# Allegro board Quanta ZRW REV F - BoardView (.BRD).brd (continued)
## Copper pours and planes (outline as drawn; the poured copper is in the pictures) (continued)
DAC_VDDC on TOP (solid shape): 18.69,109.07 18.71,109.05 18.71,108.95 18.78,108.88 19.83,108.88 19.83,108.68 18.84,108.68 18.84,108.48 19.83,108.48 19.83,108.28 18.73,108.28 18.56,108.12 18.17,108.12 18.04,108.25 18.04,109.12 18.2,109.29 18.48,109.29
DAC_VDDC on BOTTOM (solid shape): 19.22,109.47 19.22,109.37 19.24,109.34 19.24,106.73 19.14,106.63 18.25,106.63 18.2,106.68 16.95,106.68 16.85,106.78 16.85,107.31 16.98,107.44 18,107.44 18.17,107.62 18.17,109.34 18.35,109.52 19.16,109.52
EC_GND on SVCC (solid shape): 199.43,46.22 199.43,37 200.84,35.58 204.59,35.58 207.05,38.04 207.05,45.05 207.39,45.39 208.01,45.39 208.24,45.15 208.24,43.55 209.58,42.21 212.5,42.21 212.79,41.92 212.79,33.48 211.92,32.61 209.43,32.61 208.77,31.95 194.64,31.95 193.19,33.4 190.4,33.4 190.4,39.71 190.18,39.71 189.52,40.36 189.52,42.28 196.06,48.81 196.83,48.81
ECAGND on TOP (solid shape): 195.92,32.25 195.92,31.49 195.8,31.36 193.89,31.36 193.76,31.49 193.76,31.87 194.02,32.13 194.27,32.13 194.65,32.51 195.67,32.51
ECAGND on TOP (solid shape): 197.26,37.99 197.26,37.59 197.2,37.53 196.82,37.53 196.64,37.71 196.08,37.71 195.83,37.46 194.65,37.46 194.53,37.59 194.53,37.71 195.54,38.73 196.51,38.73
ECAGND on IN2 (solid shape): outline of 290 points within 193.26,31.36 196.68,38.6
HDMI_5V on TOP (solid shape): 17.24,74.5 17.24,73.32 17.12,73.19 12.39,73.19 12.2,73.39 12.2,74.48 12.36,74.64 17.1,74.64
HDMI_5V on IN2 (solid shape): 13.41,73.77 13.41,73.26 13.09,72.94 12.8,72.83 12.69,72.54 11.47,71.32 10.3,71.32 10.09,71.53 10.09,72.15 10.1,72.16 10.1,72.55 11.58,74.02 13.15,74.02
IVDDO on BOTTOM (solid shape): 17.72,106.09 17.72,106.04 17.87,105.89 17.87,105.28 17.73,105.14 17.61,105.14 17.55,105.09 17.55,104.15 17.23,103.83 16.4,103.83 16.27,103.96 16.27,106.02 16.62,106.37 17.44,106.37
IVDDO on BOTTOM (solid shape): 25.95,113.43 25.95,112.62 25.77,112.44 25.39,112.44 25.21,112.26 25.21,111.88 25.08,111.76 24.52,111.76 24.32,111.55 23.66,111.55 23.2,112.01 23.2,112.57 23.33,112.7 24.07,112.7 24.32,112.95 24.32,113.61 24.37,113.66 25.72,113.66
IVDDO on IN2 (solid shape): 26.25,113.15 26.25,112.39 25.74,111.88 24.98,111.88 24.22,112.64 24.22,113.41 24.47,113.66 25.74,113.66
IVDDO on IN2 (solid shape): 18.58,106.42 18.58,105.15 18.33,104.9 16.93,104.9 16.68,105.15 16.68,106.55 16.93,106.8 18.2,106.8
L_SPK+ on TOP (solid shape): 60.39,19.02 60.39,17.13 60.14,16.88 60.14,15.88 60,15.74 59.26,15.74 59.06,15.94 59.06,18.25 59.93,19.12 60.29,19.12
L_SPK+ on TOP (solid shape): 38.67,33.78 38.67,33.55 38.54,33.42 37.38,33.42 37.19,33.6 37.17,33.63 36.61,33.63 36.59,33.6 35.21,33.6 35.21,33.81 37.61,33.81 37.73,33.93 38.52,33.93
L_SPK+ on IN1 (solid shape): 61.09,20.04 61.09,18.13 60.89,17.93 59.96,17.93 59.82,18.06 59.82,19.86 59.84,19.9 60.24,20.29 60.85,20.29
L_SPK+ on IN1 (solid shape): 41.85,34.13 41.85,33.75 41.52,33.42 37.66,33.42 37.53,33.55 37.53,33.8 37.66,33.93 38.98,33.93 39.05,33.93 39.51,34.39 41.59,34.39
L_SPK+_1 on TOP (solid shape): 61.73,16.58 61.73,14.27 61.55,14.09 60.71,14.09 60.61,14.19 60.61,16.76 61.55,16.76
L_SPK+_1 on BOTTOM (solid shape): 62.7,17.09 62.7,14.47 61.99,13.76 61.56,13.76 61.21,14.11 60.71,14.11 60.59,14.24 60.59,15.13 60.84,15.38 61.91,15.38 62.09,15.56 62.09,17.09 62.12,17.12 62.67,17.12
L_SPK- on TOP (solid shape): 63.33,19.31 63.33,17.88 63.12,17.67 63.12,17.46 63.05,17.39 61.88,17.39 61.69,17.58 61.69,19.31 61.86,19.48 63.16,19.48
L_SPK- on TOP (solid shape): 38.67,34.62 38.67,34.21 38.54,34.08 37.68,34.08 37.6,34.01 36.2,34.01 36.2,34 35.21,34 35.21,34.21 36.2,34.21 36.24,34.2 36.24,34.21 37.38,34.21 37.66,34.49 37.66,34.6 37.8,34.74 38.54,34.74
L_SPK- on IN1 (solid shape): 63.25,20.72 63.25,19.07 62.87,18.69 61.86,18.69 61.6,18.94 61.6,19.93 61.78,20.11 61.78,20.11 62.52,20.84 63.13,20.84
L_SPK- on IN1 (solid shape): 41.03,35.28 41.03,35 40.79,34.76 39.45,34.76 38.87,34.18 37.81,34.18 37.63,34.36 37.63,34.62 37.76,34.74 38.44,34.74 39.18,35.48 40.83,35.48
L_SPK-_1 on TOP (solid shape): 63.07,16.83 63.07,14.55 63.2,14.42 63.2,13.55 62.99,13.34 62.22,13.34 62.03,13.53 62.03,16.81 62.14,16.91 63,16.91
L_SPK-_1 on BOTTOM (solid shape): 63.81,17.05 63.81,13.53 63.38,13.1 62.49,13.1 62.28,13.31 62.28,13.67 63.03,14.42 63.03,14.43 63.09,14.49 63.09,17.04 63.17,17.12 63.74,17.12
LAN_MCT1 on TOP (solid shape): 17.84,90.17 17.84,89.53 17.72,89.4 17.08,89.4 17.05,89.41 17.04,89.43 16.67,89.43 16.44,89.66 16.44,90.89 16.68,91.13 16.88,91.13
LAN_MCT2 on TOP (solid shape): 18,87.37 18,86.74 17.87,86.61 17.23,86.61 17.21,86.62 17.19,86.63 16.95,86.85 16.64,86.96 16.62,86.97 16.47,87.12 16.47,87.98 16.83,88.34 17.03,88.34
LAN_MCT3 on TOP (solid shape): 18.02,84.25 18.02,83.31 17.13,82.42 16.52,82.42 16.42,82.52 16.42,84.04 16.82,84.04 16.93,84.15 16.95,84.15 17.18,84.37 17.89,84.37
LANVCC on TOP (solid shape): 35.4,83.14 36.25,82.29 36.25,81.6 35.91,81.25 35.14,81.25 34.86,81.53 34.86,83.43 35.14,83.71 35.14,84.02 35.14,84.45 35.2,84.51 35.2,85.51 35.4,85.51
LANVCC on TOP (solid shape): 32.6,95.75 32.6,94.61 31.84,93.85 31.84,91.57 31.84,91.57 31.84,91.31 32.35,90.8 32.73,90.8 33.82,89.71 34.6,89.71 34.6,88.72 34.43,88.72 34.4,88.75 33.9,89.25 33.64,89.25 32.92,89.97 32.83,89.97 32.77,90.01 32.7,90.04 32.68,90.04 32.48,90.25 31.65,90.25 31.19,89.78 30.31,89.78 30.19,89.91 30.19,95.25 30.95,96.01 32.35,96.01
LANVCC on TOP (solid shape): 44.84,93.16 44.84,90.29 43.94,89.39 43.94,88.48 43.83,88.36 41.44,88.36 40.96,87.88 39.48,87.88 39.35,88.02 37.51,88.02 37.51,88.22 38.5,88.22 38.6,88.31 38.6,88.32 39.03,88.74 39.38,88.74 39.48,88.85 40.3,88.85 40.5,89.05 40.5,89.28 40.73,89.51 41.47,89.51 41.67,89.71 42.43,89.71 42.63,89.91 42.63,90.93 42.09,91.47 41.78,91.47 41.24,92.02 41.24,93.14 41.34,93.24 44.77,93.24
LANVCC on BOTTOM (solid shape): 32.73,96.52 32.73,95.37 31.71,94.36 30.44,94.36 30.19,94.61 30.19,95.12 31.84,96.77 32.47,96.77
LANVCC on BOTTOM (solid shape): 45.55,93.72 45.55,87.5 45.3,87.24 44.79,87.24 44.54,87.5 44.54,88.51 44.28,88.77 43.4,88.77 42.25,89.91 42.25,93.72 42.76,94.23 45.05,94.23
LANVCC on IN1 (solid shape): 43.78,91.97 43.78,86.62 43.76,86.61 43.76,86.08 39.23,81.55 37.28,81.55 37.19,81.45 35.72,81.45 35.67,81.5 35.67,82.62 35.73,82.68 35.91,82.68 36.04,82.66 36.17,82.68 36.78,82.68 36.92,82.82 36.92,82.82 37.51,83.41 38.86,83.41 42.33,86.89 42.47,86.98 42.58,87.24 42.56,87.37 42.56,87.83 42.58,87.96 42.56,88.08 42.56,90.03 42.46,90.14 42.46,92.02 42.58,92.15 43.6,92.15
LCDVCC on TOP (solid shape): 124.29,186.3 125.44,186.3 125.47,186.3 125.48,186.28 126.15,185.95 126.83,186.28 126.84,186.29 126.86,186.3 130.39,186.3 130.64,186.05 130.64,184.91 129.76,184.02 124.17,184.02 122.77,185.42 119.85,185.42 119.6,185.16 118.2,185.16 117.82,185.54 117.82,186.56 119.09,187.83 122.77,187.83
LCDVCC_R on TOP (solid shape): 132.55,186.56 132.55,184.78 132.4,184.63 132.37,184.62 132.1,184.66 131.89,184.54 131.88,184.53 131.86,184.53 131.53,184.53 131.28,184.78 131.28,186.69 131.53,186.94 132.17,186.94
LCDVCC_R on BOTTOM (solid shape): 130.93,186.74 131.36,186.74 131.53,186.91 132.37,186.91 132.65,186.64 132.65,185.85 132.37,185.57 130.22,185.57 129.22,186.99 129.22,187.04 129.4,187.17 129.41,187.17 130.06,186.24 130.07,186.24 130.26,186.38 130.26,186.38 129.61,187.3 129.61,187.32 129.8,187.45 129.82,187.45 130.46,186.53 130.48,186.53 130.67,186.66 130.67,186.67 130.02,187.59 130.02,187.6 130.22,187.74 130.23,187.74
NV_PLLVDD on TOP (solid shape): outline of 108 points within 183.89,142.44 185.94,150.8
PEX_PLLVDD on IN2 (solid shape): 172.45,160.11 172.73,159.75 173.15,159.91 173.24,159.95 173.32,159.91 173.49,159.78 173.71,159.76 174.07,159.4 174.26,158.94 174.75,159.06 174.84,159.1 174.92,159.05 175.17,158.86 175.48,158.93 176.04,158.93 176.54,158.43 176.54,157.55 176.28,157.29 175.91,157.29 175.63,157.57 175.63,157.6 175.5,157.94 175.15,158.01 175.14,158.01 174.46,158.01 174.45,158.01 174.02,158.44 174.02,158.46 173.78,158.82 173.36,158.72 172.35,158.72 171.55,159.52 171.55,159.53 169.88,161.19 167.83,161.19 167.56,161.46 167.56,161.8 167.63,161.87 170.69,161.87
PHASE_A on BOTTOM (solid shape): 147.92,169.03 147.92,167.76 147.28,167.13 146.82,167.13 146.77,167.18 146.77,167.76 147.03,168.02 147.03,169.03 147.15,169.16 147.79,169.16
PHASE_A on BOTTOM (solid shape): 147.77,162.61 147.77,158.99 147.46,158.68 145.55,158.68 145.27,158.97 145.27,159.73 145.28,159.74 145.28,160.47 145.26,160.47 145.26,160.65 144.73,160.65 144.73,160.47 144.72,160.47 144.72,158.96 144.44,158.68 142.31,158.68 142.12,158.88 142.12,160.65 143.37,161.91 143.37,162.23 143.54,162.4 144.65,162.4 145,162.75 145,163.04 145.15,163.18 147.2,163.18
PHASE_B1 on BOTTOM (solid shape): 127.72,170.3 127.72,169.54 127.47,169.29 127.47,168.91 127.09,168.52 126.63,168.52 126.58,168.58 126.58,170.18 126.83,170.43 127.6,170.43
PHASE_B1 on BOTTOM (solid shape): 129.25,162.68 129.25,160.72 128.87,160.34 127.74,160.34 127.7,160.36 127.69,160.39 127.69,161.92 127.15,161.92 127.15,160.39 127.14,160.36 127.1,160.34 124.86,160.34 124.37,160.83 124.37,163.98 124.96,164.58 127.36,164.58
PHASE_B2 on BOTTOM (solid shape): 136.99,169.16 136.99,167.89 136.36,167.25 135.9,167.25 135.85,167.31 135.85,167.89 136.23,168.27 136.23,169.16 136.36,169.29 136.87,169.29
PHASE_B2 on BOTTOM (solid shape): 138.61,161.32 138.61,159.26 138.27,158.92 137.05,158.92 136.59,159.38 136.59,160.59 136.58,160.6 136.58,160.78 136.04,160.78 136.04,160.61 136.03,160.59 136.03,159.45 135.49,158.92 134.02,158.92 133.62,159.32 133.62,162 134.23,162.62 134.23,163.26 134.25,163.29 134.28,163.31 136.62,163.31
PHASE_C on BOTTOM (solid shape): 158.97,169.03 158.97,167.89 158.2,167.13 157.62,167.13 157.57,167.18 157.57,168.91 157.82,169.16 158.84,169.16
PHASE_C on BOTTOM (solid shape): 159.6,162.01 159.6,159.22 159.04,158.65 157.76,158.65 157.59,158.83 157.59,160.46 157.58,160.47 157.58,160.65 157.05,160.65 157.05,160.48 157.03,160.48 157.03,158.87 156.82,158.66 155.3,158.66 154.84,159.12 154.84,161.39 155.95,162.49 155.95,163.13 155.96,163.16 156,163.18 158.43,163.18
R_SPK+ on TOP (solid shape): 67.6,19.2 67.6,17.3 66.75,17.3 66.75,17.16 66.07,17.16 65.79,17.44 65.79,19.29 65.93,19.43 67.37,19.43
R_SPK+ on TOP (solid shape): 37.55,35.94 37.55,35.76 37.27,35.48 37.27,35.15 36.93,34.8 35.21,34.8 35.21,35.01 36.57,35.01 36.77,35.2 36.77,35.4 37.05,35.68 37.05,35.89 37.22,36.06 37.43,36.06
R_SPK+ on IN1 (solid shape): 67.56,19.04 67.56,16.8 66.66,15.9 65.26,15.9 65.16,16 65.16,17.54 65.54,17.92 65.54,19.07 65.93,19.45 67.14,19.45
R_SPK+ on IN1 (solid shape): 39.71,38.6 39.71,38.07 38.28,36.63 37.79,36.59 37.75,36.1 37.25,35.61 37.25,35.56 37.21,35.52 37.21,34.96 37.05,34.79 36.54,34.79 36.41,34.92 36.41,36.83 38.32,38.73 39.59,38.73
R_SPK+_1 on TOP (solid shape): 67.57,16.78 67.57,13.61 67.44,13.48 66.68,13.48 66.55,13.61 66.55,16.83 66.58,16.86 67.49,16.86
R_SPK+_1 on BOTTOM (solid shape): 65.82,17.04 65.82,15.64 65.97,15.5 67.35,15.5 67.57,15.28 67.57,13.61 67.42,13.45 66.64,13.45 66.13,13.96 65.44,13.96 65.09,14.31 65.09,17.06 65.17,17.14 65.72,17.14
R_SPK- on TOP (solid shape): 65.31,18.53 65.31,17.57 65.16,17.42 64.01,17.42 63.86,17.57 63.86,17.67 63.61,17.92 63.61,18.56 63.91,18.86 64.98,18.86
R_SPK- on TOP (solid shape): 38.52,35.43 38.52,35.12 38.29,34.9 37.76,34.9 37.51,34.64 37.51,34.63 37.28,34.4 35.21,34.4 35.21,34.61 36.99,34.61 37.41,35.04 37.41,35.37 37.6,35.56 38.39,35.56
R_SPK- on IN1 (solid shape): 65.03,19.7 65.03,17.8 64.65,17.42 63.89,17.42 63.86,17.44 63.79,17.75 63.51,17.9 63.51,19.45 63.89,19.83 64.9,19.83
R_SPK- on IN1 (solid shape): 41.74,37.97 41.74,37.53 41.66,37.45 41.61,37.35 40.04,35.78 39.1,35.78 38.39,35.07 37.53,35.07 37.46,35.14 37.46,35.42 37.99,35.94 38.33,36.05 38.44,36.39 38.65,36.6 39.08,36.6 39.31,36.83 39.5,36.83 39.9,36.99 39.9,37.42 40.58,38.1 41.62,38.1
R_SPK-_1 on TOP (solid shape): 65.34,16.83 65.34,13.5 65.03,13.2 64.45,13.2 64.29,13.35 64.29,16.78 64.4,16.88 65.28,16.88
R_SPK-_1 on BOTTOM (solid shape): 64.7,17.07 64.7,14.41 65.24,13.87 65.24,13.56 64.81,13.13 64.18,13.13 64.09,13.22 64.09,17.07 64.16,17.14 64.63,17.14
REGOUT on TOP (solid shape): 40.81,93.11 40.81,91.36 40.2,90.75 40.2,90.52 40.09,90.42 39.71,90.42 39.47,90.18 39.47,89.24 39.13,88.9 38.77,88.9 38.5,88.62 38.5,88.42 37.51,88.42 37.51,88.59 37.73,88.81 37.73,90.29 39.28,91.84 39.28,93.06 39.41,93.19 40.73,93.19
RING2 on TOP (solid shape): 18.5,12.7 18.5,12.04 18.61,11.93 19.01,11.93 19.27,11.68 19.27,11.55 19.09,11.38 17.56,11.38 17.46,11.48 17.46,12.24 17.31,12.39 17.31,12.72 17.46,12.87 18.33,12.87
RING2 on TOP (solid shape): 28.84,35.51 28.84,34.77 29,34.61 30,34.61 30,34.41 30,34.4 29.01,34.4 28.79,34.4 28.28,34.91 28.28,35 28.08,35.2 27.72,35.2 27.6,35.33 27.6,35.63 27.75,35.78 28.56,35.78
RING2 on BOTTOM (solid shape): 18.5,14.09 18.5,12.57 18.25,12.31 17.36,12.31 17.11,12.57 17.11,14.09 17.23,14.22 18.38,14.22
RING2 on BOTTOM (solid shape): outline of 230 points within 27.19,28.09 31.53,36.7
RING2_R on TOP (solid shape): 17.16,11.91 17.16,11.12 17.49,10.79 18.38,10.79 18.5,10.66 18.5,9.93 18.32,9.75 14.95,9.75 14.66,10.04 14.66,10.96 15.25,11.55 15.25,11.88 15.33,11.96 17.11,11.96
RING2_R on IN1 (solid shape): 15.71,11.17 15.71,10.03 15.46,9.77 14.82,9.77 14.57,10.03 14.57,11.17 14.95,11.55 15.33,11.55
RREF on TOP (solid shape): 59.31,25.78 59.5,25.69 59.71,25.72 59.78,25.65 59.78,24.89 59.48,24.59 58.84,24.59 58.84,25.58 59.04,25.78
RX_AVCC on BOTTOM (solid shape): 26.12,110.99 26.12,106.47 25.79,106.14 24.75,106.14 24.6,106.29 24.6,111.5 25.62,111.5
RX_IVDD on TOP (solid shape): 20.23,105.49 20.23,105.49 20.23,104.72 20.05,104.54 19.62,104.54 19.44,104.72 19.44,105.02 19.6,105.18 19.85,105.18 20.03,105.36 20.03,106.48 20.23,106.48
RX_IVDD on BOTTOM (solid shape): 22.64,112.85 22.64,112.01 22.39,111.76 20.23,111.76 20.1,111.88 20.1,112.39 20.43,112.72 21.96,112.72 22.11,112.87 22.62,112.87
RX_IVDD on BOTTOM (solid shape): 19.37,106.04 19.37,105.63 19.44,105.56 19.44,105.25 19.34,105.15 18.91,105.15 18.83,105.08 18.83,104.29 18.78,104.24 18.02,104.24 18.02,105.66 18.53,106.17 19.24,106.17
RX_IVDD33 on TOP (solid shape): 26.99,112.87 26.99,110.13 26.17,110.13 26.05,110.26 25.54,110.26 25.46,110.18 25.34,110.18 25.34,111.17 26.28,112.11 26.28,112.82 26.4,112.95 26.91,112.95
S5D on BOTTOM (solid shape): 81.34,35.22 81.34,34.11 81.07,33.84 80.31,33.84 80.2,33.94 80.2,35.43 80.3,35.53 81.03,35.53
SLEEVE on TOP (solid shape): 28.62,34.21 30,34.21 30,34 28.91,34 28.8,33.9 27.55,33.9 27.39,34.05 27.39,34.67 27.52,34.79 28.03,34.79
SLEEVE on TOP (solid shape): 17.97,20.19 18,20.19 18.12,20.06 18.66,20.06 18.78,19.93 18.78,19.66 18.02,18.89 17.11,18.89 16.75,18.54 16.45,18.54 16.32,18.66 16.32,19.5 16.47,19.66 16.95,19.66 17.13,19.83 17.13,20.49 17.18,20.54 17.61,20.54
SLEEVE on BOTTOM (solid shape): 17.01,20.48 17.01,18.57 16.63,18.2 15.78,18.2 15.54,18.44 15.54,20.63 15.94,21.03 16.45,21.03
SLEEVE on BOTTOM (solid shape): 28.41,34.41 28.41,33.65 27.77,33.02 27.77,32.25 27.65,32.13 26.76,32.13 26.38,32.51 26.38,33.52 26.5,33.52 26.51,33.47 26.52,33.41 26.54,33.36 26.57,33.31 26.6,33.27 26.64,33.23 26.69,33.2 26.74,33.17 26.79,33.15 26.84,33.14 26.9,33.14 26.96,33.15 27.01,33.16 27.06,33.18 27.11,33.21 27.15,33.25 27.19,33.29 27.22,33.34 27.24,33.39 27.26,33.44 27.27,33.5 27.27,33.55 27.26,33.61 27.24,33.66 27.22,33.71 27.19,33.76 27.15,33.8 27.11,33.83 27.06,33.86 27.01,33.89 26.96,33.9 26.9,33.91 26.84,33.9 26.79,33.89 26.74,33.88 26.69,33.85 26.64,33.82 26.6,33.78 26.57,33.73 26.54,33.69 26.52,33.63 26.51,33.58 26.5,33.52 26.38,33.52 26.38,34.16 27.01,34.79 28.03,34.79
SLEEVE_R on TOP (solid shape): 16.7,20.52 16.7,20.14 16.65,20.09 16.04,20.09 15.66,19.71 15.15,19.71 15.02,19.83 13.65,19.83 13.04,20.44 13.04,20.57 13.27,20.8 14.74,20.8 15.48,21.54 15.68,21.54
SM_RCOMP_0 on IN1 (solid shape): outline of 236 points within 145.63,110.61 147.54,114.17
SM_RCOMP_1 on IN1 (solid shape): 147.75,112.64 147.84,112.6 147.85,112.51 147.85,112.32 147.94,112.15 147.97,112.08 147.84,111.76 147.97,111.43 147.94,111.36 147.84,111.03 148.06,110.77 148.07,110.77 148.42,110.41 148.42,109.98 148.04,109.6 147.79,109.6 147.61,109.78 147.61,111.57 147.62,111.93 147.31,112.13 147.29,112.13 147.15,112.26 147.15,112.52 147.28,112.64
SP_PLLVDD on TOP (solid shape): 184.7,151.23 184.7,150.87 184.52,150.69 184.19,150.69 183.65,150.16 183.65,142.46 183.58,142.39 183.17,142.39 183.02,142.54 183.02,142.87 182.36,143.53 182.36,144.19 182.49,144.32 182.49,146.1 182.77,146.38 182.77,147.01 182.46,147.32 182.46,148.79 182.87,149.2 182.87,150.49 183.64,151.27 184.66,151.27
SYSTEM_AGND on TOP (solid shape): 68.95,57.96 68.95,57.07 68.88,57 68.06,57 67.86,57.21 67.86,57.34 67.78,57.51 67.63,57.57 67.61,57.58 67.09,57.58 66.87,57.81 66.87,58.31 66.66,58.52 65.04,58.52 64.92,58.4 64.92,57.78 64.77,57.62 63.98,57.62 63.87,57.73 63.87,58.27 63.87,58.27 63.87,58.91 64.09,59.13 67.78,59.13
TERM9 on TOP (solid shape): 20.79,98.04 20.79,83.56 20.41,83.18 18.88,83.18 18.5,83.56 18.5,98.04 18.76,98.29 20.54,98.29
TERM9 on BOTTOM (solid shape): 24.22,98.93 24.22,95.96 24.07,95.8 20.03,95.8 19.65,96.19 19.65,98.93 19.91,99.2 23.95,99.2
TH_FAN_POWER on TOP (solid shape): 56.48,111.76 56.48,111.25 55.59,110.36 54.7,110.36 54.32,109.98 51.78,109.98 51.65,110.1 51.65,110.36 51.78,110.49 53.68,110.49 55.08,111.88 56.35,111.88
TP_PWR on TOP (solid shape): 134.32,190 134.32,189.01 134.33,189.01 134.33,187.32 134.07,187.07 132.93,187.07 132.68,187.32 132.68,190.11 132.93,190.37 133.95,190.37
TP_PWR on BOTTOM (solid shape): 132.61,187.83 134.07,187.83 134.37,187.53 134.37,187.21 134.58,187.01 134.58,186.69 134.45,186.56 132.96,186.56 132.46,187.05 132.23,187.05 131.25,188.45 131.25,188.47 131.43,188.59 131.46,188.59 132.1,187.68 132.12,187.68 132.3,187.8 132.3,187.83 131.66,188.74 131.66,188.75 131.86,188.89
USBPWR0 on TOP (solid shape): 14.61,32.09 15.26,32.09 15.28,32.07 15.28,32.05 15.33,32 15.33,31.87 15.2,31.75 14.82,31.75 14.29,31.21 13.96,31.21 13.73,31.44 13.73,31.57 14.06,31.89 14.06,32.09 14.16,32.19 14.51,32.19
USBPWR0 on TOP (solid shape): 19.6,40.74 19.6,40.48 19.55,40.43 19.55,38.93 19.55,38.86 19.55,37.62 19.54,37.56 19.54,37.35 19.22,37.03 17.44,37.03 17.4,37.05 17.39,37.06 17.11,37.19 16.82,37.06 16.81,37.05 16.77,37.03 16.29,37.03 16.26,37 16.25,36.99 16.19,36.95 16.14,36.89 16.14,36.87 16.09,36.83 16.09,35.67 15.73,35.31 15.48,35.31 13.7,33.52 13.7,33.01 13.31,32.63 12.9,32.63 12.53,33 12.53,34.16 13.8,35.43 13.8,35.68 13.81,35.7 13.93,36.11 13.8,36.51 13.8,37.05 13.98,37.23 13.98,39.95 14.31,40.28 16.85,40.28 17.13,40 18,40 18.32,40.32 18.32,40.64 18.46,40.78 19.06,40.78 19.12,40.78 19.18,40.8 19.53,40.8
USBPWR0 on BOTTOM (solid shape): 16.57,38.27 16.57,34.69 15.48,33.6 15.48,32.06 14.61,31.19 13.91,31.19 13.2,31.9 12.94,31.9 12.48,32.36 12.48,33.6 13.98,35.1 13.98,38.25 14.36,38.63 16.22,38.63
USBPWR1 on TOP (solid shape): 23.24,55.18 23.24,54.11 22.54,53.41 22.54,51.59 22.12,51.16 20.93,51.16 20.91,51.16 20.54,51.16 20.35,51.13 20.19,51.02 20.08,50.92 19.99,50.78 19.94,50.63 19.94,50.61 19.91,50.58 19.68,50.58 19.51,50.41 18.46,50.41 18.44,50.42 18.42,50.43 18.1,50.6 17.75,50.51 17.72,50.49 17.69,50.51 17.33,50.6 17.01,50.43 16.99,50.42 16.97,50.41 16.47,50.41 16.27,50.21 16.27,49.17 16.33,49.11 16.34,49.1 16.52,48.88 16.79,48.8 17,48.8 17.16,48.64 17.16,48.13 17.01,47.98 15.99,47.98 15.71,48.26 15.71,49.02 15.46,49.27 14.34,49.27 14.21,49.4 14.21,49.42 13.96,49.68 13.27,49.68 12.66,50.29 12.66,51.94 13.17,52.45 17.69,52.45 18.15,52.9 18.15,53.64 18.16,53.67 18.19,53.69 19.74,54.25 21.02,55.29 21.03,55.3 21.05,55.3 21.13,55.3 21.15,55.32 23.11,55.32
USBPWR1 on IN1 (solid shape): 18.25,52.12 18.25,50.87 17.78,50.4 17.71,50.37 17.64,50.4 17.34,50.49 17.08,50.33 17.06,50.32 17.04,50.31 13.02,50.31 12.67,50.66 12.67,51.93 13.04,52.29 18.07,52.29
USBPWR2 on BOTTOM (solid shape): 215.16,25.9 215.17,25.83 215.2,25.69 215.24,25.56 215.29,25.42 215.34,25.29 215.41,25.16 215.48,25.03 215.55,24.91 215.64,24.8 215.73,24.69 215.82,24.58 215.93,24.48 216.04,24.39 216.15,24.3 216.27,24.22 216.39,24.15 216.52,24.08 216.65,24.02 216.79,23.97 216.92,23.93 217.06,23.89 217.2,23.87 217.27,23.86 217.51,23.62 217.51,19.68 217.13,19.3 214.73,19.3 214.13,18.7 214.1,18.69 214.06,18.67 214.03,18.65 214,18.62 213.97,18.58 213.96,18.54 213.95,18.52 213.81,18.38 213,18.38 212.9,18.48 212.9,19.02 213.15,19.28 213.61,19.28 213.94,19.6 216.87,19.6 216.87,19.8 215.57,19.8 215.57,19.6 213.94,19.6 213.96,19.62 213.96,20.1 216.87,20.1 216.87,20.3 215.57,20.3 215.57,20.1 213.96,20.1 213.96,20.6 216.87,20.6 216.87,20.8 215.57,20.8 215.57,20.6 213.96,20.6 213.96,21.1 216.87,21.1 216.87,21.3 215.57,21.3 215.57,21.1 213.96,21.1 213.96,21.29 213.58,21.67 213.58,22.22 212.94,22.86 212.18,22.86 211.22,23.81 211.22,25.76 211.37,25.9
V_BLIGHT on TOP (solid shape): 125.41,189.97 126.99,189.97 126.99,189.99 127.22,189.99 128.1,189.1 128.1,187.19 127.6,186.69 127.47,186.69 126.71,187.45 126.7,187.45 126.68,187.46 126.15,187.64 125.62,187.45 124.55,187.45 123.41,188.59 123.41,189.73 123.64,189.97 124.96,189.97 124.96,189.99 125.41,189.99
V_BLIGHT on BOTTOM (solid shape): 128.16,187.91 128.16,186.34 128.83,185.38 128.62,185.23 127.97,186.17 127.77,186.03 128.42,185.09 128.21,184.94 127.34,186.19 127.34,186.94 126.71,187.57 126.71,188.08 126.83,188.21 127.85,188.21
VA on TOP (solid shape): 222.08,199.13 222.08,192.27 221.07,191.26 218.53,191.26 218.02,191.77 218.02,199.39 218.4,199.77 221.45,199.77
VA on BOTTOM (solid shape): 223.61,197.1 223.61,190.75 223.1,190.24 218.02,190.24 217.89,190.37 217.89,197.48 218.27,197.86 222.85,197.86
VA1 on TOP (solid shape): 220.18,190.62 220.18,186.81 219.67,186.3 216.12,186.3 215.35,187.07 215.35,190.37 215.86,190.88 219.93,190.88
VA1 on BOTTOM (solid shape): 223.74,189.48 223.74,185.29 223.35,184.91 218.65,184.91 218.36,185.19 213.29,185.19 212.94,185.54 212.94,188.08 212.81,188.21 212.31,188.21 212.18,188.34 212.18,188.72 213.45,189.99 223.23,189.99
VA2 on BOTTOM (solid shape): 224.5,183.98 224.5,178.18 224.37,178.05 220.81,178.05 220.18,178.68 220.18,180.84 219.74,181.29 215.28,181.29 215.13,181.44 215.13,184.05 215.31,184.23 224.25,184.23
VL on BOTTOM (solid shape): 66.55,50.84 66.55,49.54 66.51,49.5 65.77,49.5 65.65,49.61 65.65,49.97 65.6,50.02 65.6,51.24 65.78,51.43 65.96,51.43
VREFC_VMA1 on IN1 (solid shape): outline of 176 points within 212.38,169.29 218.58,171.56
N16779422 on TOP (solid shape): 208.62,27.35 208.62,25.59 208.58,25.5 208.49,25.49 208.06,25.34 208.1,24.89 208.1,24.69 207.82,24.41 205.24,24.41 205.19,24.46 205.19,27.61 205.26,27.68 205.29,27.68 208.29,27.68
N16779422 on BOTTOM (solid shape): 208.62,27.17 208.62,26.79 208.5,26.67 206.21,26.67 205.96,26.41 203.92,26.41 203.92,26.41 203.03,26.41 202.78,26.66 202.78,26.67 202.73,26.71 202.73,27.31 202.85,27.43 208.37,27.43
N17023337 on IN2 (solid shape): 28.8,93.59 28.8,93.57 28.8,93.55 28.83,93.3 29.01,93.12 29.03,93.11 29.04,93.09 29.04,92.75 29.03,92.72 29,92.7 28.66,92.32 29,91.95 29.03,91.93 29.04,91.9 29.04,91.07 28.99,90.98 28.88,90.99 28.28,90.67 28.88,90.36 28.99,90.37 29.04,90.28 29.04,89.68 29.03,89.66 29.01,89.65 28.79,89.3 29.01,88.95 29.03,88.95 29.04,88.92 29.04,88.8 28.94,88.7 28.94,83.46 28.79,83.31 26.25,83.31 26,83.56 26,93.47 26.63,94.1 28.28,94.1
N17047087 on TOP (solid shape): 185.25,197.47 185.25,195.83 185.21,195.79 183.08,195.79 182.56,196.31 178.71,196.31 178.08,195.68 177.98,195.58 177.17,195.58 176.87,195.87 176.87,199.39 177.12,199.64 179.16,199.64 179.79,200.27 179.79,201.02 179.95,201.18 181.55,201.18
N17047087 on BOTTOM (solid shape): 184.87,201.29 184.87,196.59 184.62,196.34 184.11,196.34 183.6,196.85 181.19,196.85 179.79,198.24 179.41,198.24 179.29,198.37 179.29,201.29 179.58,201.58 180.01,201.58 180.1,201.67 184.49,201.67
N17055599 on BOTTOM (solid shape): 184.88,58.71 184.88,56.58 184.77,56.47 184.14,56.47 184.03,56.58 184.03,58.71 184.16,58.84 184.74,58.84
N17055737 on BOTTOM (solid shape): 179.91,63.01 179.91,62.27 179.83,62.2 177.76,62.2 177.71,62.25 177.71,63.03 177.76,63.08 179.83,63.08
N17067390 on BOTTOM (solid shape): 104.33,140.1 103.21,138.98 103.21,138.12 103.06,137.97 102.65,137.97 101.89,138.73 101.89,140.41 103.26,141.78 104.33,141.78
N17069186 on TOP (solid shape): 197.74,106.89 197.74,104.19 197.64,104.09 196.91,104.09 196.81,104.2 196.81,107.03 196.96,107.18 197.45,107.18
N17069439 on TOP (solid shape): 207.9,106.3 207.9,104.2 207.83,104.13 207.09,104.13 206.97,104.24 206.97,106.26 207.08,106.37 207.83,106.37
N17071762 on TOP (solid shape): 216.37,119.38 216.37,117.47 216.24,117.34 215.73,117.34 215.61,117.47 215.61,119.38 215.73,119.5 216.24,119.5
N17071926 on BOTTOM (solid shape): 187.79,65.69 187.79,64.78 188.19,64.38 188.19,63.74 188.11,63.66 187.7,63.66 187.61,63.74 186.76,63.74 186.5,64 186.5,64.74 186.78,65.02 186.78,65.72 186.89,65.83 187.66,65.83
N17410561 on BOTTOM (solid shape): 65.06,96.89 65.1,96.87 65.12,96.84 65.12,87.66 64.73,87.27 64.73,87.24 64.71,87.21 64.68,87.19 61.46,87.19 61.04,87.62 61.04,89.59 61.57,90.12 61.57,94.66 63.79,96.89
N17721246 on TOP (solid shape): 122.14,167.64 123.02,167.64 123.15,167.51 123.15,166.87 123.02,166.75 121.75,166.75 121.12,167.38 121.12,168.02 121.25,168.14 121.63,168.14
N17721246 on BOTTOM (solid shape): 123.66,168.78 123.66,168.14 123.53,168.02 122.39,168.02 122.01,167.64 121.37,167.64 121.25,167.76 121.25,168.14 121.37,168.27 121.63,168.27 122.39,169.03 123.41,169.03
N17721295 on BOTTOM (solid shape): 132.4,169.21 132.4,168.8 132.93,168.27 132.93,167.64 132.8,167.51 132.68,167.51 132.42,167.76 131.91,167.76 131.41,167.25 131.15,167.25 131.03,167.38 131.03,168.02 131.66,168.65 131.66,169.11 131.94,169.39 132.22,169.39
N17723254 on BOTTOM (solid shape): 155.37,167.62 155.37,167.02 155.35,166.98 155.32,166.97 154.84,166.97 154.84,166.72 155.33,166.72 155.37,166.71 155.38,166.67 155.38,166.52 155.37,166.48 155.33,166.47 154.82,166.47 154.53,166.76 153.61,166.76 153.56,166.81 153.56,167.75 153.65,167.84 155.15,167.84
N17762566 on BOTTOM (solid shape): 143.85,167.51 143.85,167 143.73,166.87 143.47,166.87 143.34,167 142.58,167 142.33,166.75 141.82,166.75 141.69,166.87 141.69,167.92 141.8,168.02 143.34,168.02
N17763940 on BOTTOM (solid shape): 146.77,169.03 146.77,168.4 146.52,168.14 146.39,168.14 146.01,167.76 146.01,167.18 145.96,167.13 145.81,167.13 145.76,167.18 145.76,169.03 145.88,169.16 146.65,169.16
N17766069 on BOTTOM (solid shape): 129.5,172.41 129.5,172.03 129.12,171.65 129.12,169.79 128.99,169.67 128.36,169.67 128.23,169.79 128.23,171.7 129.1,172.56 129.35,172.56
N17766091 on BOTTOM (solid shape): 127.72,171.57 127.72,171.06 127.6,170.94 126.71,170.94 126.2,170.43 126.2,169.67 125.82,169.29 125.82,168.58 125.77,168.52 125.62,168.52 125.56,168.58 125.56,170.81 126.45,171.7 127.6,171.7
N17768675 on BOTTOM (solid shape): 136.99,170.56 136.99,169.92 136.87,169.79 135.09,169.79 134.84,170.05 134.84,170.56 134.96,170.68 136.87,170.68
N17768697 on BOTTOM (solid shape): 135.72,169.16 135.72,168.27 135.47,168.02 135.22,168.02 135.09,167.89 135.09,167.31 135.04,167.25 134.89,167.25 134.84,167.31 134.84,169.03 135.09,169.29 135.6,169.29
N17776833 on BOTTOM (solid shape): 157.67,170.68 158.33,170.68 158.46,170.56 158.46,169.79 158.33,169.67 156.55,169.67 156.43,169.79 156.43,171.27 156.58,171.42 156.93,171.42
N17777054 on BOTTOM (solid shape): 157.31,169.03 157.31,168.14 157.06,167.89 156.93,167.89 156.81,167.76 156.81,167.18 156.76,167.13 156.6,167.13 156.55,167.18 156.55,168.02 156.43,168.14 156.43,169.03 156.55,169.16 157.19,169.16
N17828598 on BOTTOM (solid shape): 147.92,170.56 147.92,169.79 147.79,169.67 146.01,169.67 145.88,169.79 145.88,171.09 146.27,171.47 147,171.47
N19011701 on BOTTOM (solid shape): 60.83,78.9 60.83,78.1 60.75,78.02 59.59,78.02 59.47,77.9 59.47,77.44 59.19,77.16 58.81,77.16 58.53,77.44 58.53,78.74 58.78,78.99 60.75,78.99
N19018012 on BOTTOM (solid shape): 149.97,122.8 150.06,122.72 150.18,122.7 150.2,122.7 150.43,122.47 150.75,122.47 150.75,122.41 150.81,122.22 150.95,122.09 151.04,122.06 151.13,122.06 151.2,122.04 151.24,121.99 151.23,121.88 151.26,121.78 151.26,121.76 151.26,121.63 151.44,121.46 151.44,121.4 151.45,121.33 151.45,121.1 151.35,121.06 150.96,121.06 150.95,121.07 150.83,121.1 150.71,121.07 150.7,121.06 150.31,121.06 150.29,121.07 150.18,121.1 150.06,121.07 150.05,121.06 149.92,121.06 149.67,121.31 149.67,121.67 149.8,121.87 149.71,122.1 149.71,122.16 149.67,122.19 149.67,122.73 149.74,122.8
N19940934 on BOTTOM (solid shape): 71.96,53.74 72.79,53.74 72.85,53.67 72.85,53.24 71.86,52.25 71.86,51.78 71.81,51.73 70.99,51.73 70.94,51.77 70.94,53.73 70.99,53.79 71.91,53.79
N19941230 on BOTTOM (solid shape): 60.56,53.37 60.58,53.35 60.63,53.35 60.68,53.3 60.68,51.01 60.35,50.69 60.33,50.68 59.83,50.68 59.71,50.8 59.71,53.31 59.77,53.37 60.46,53.37

Small or netless copper shapes (teardrops, artwork), in the pictures only: 135 on TOP, 25 on BOTTOM, 106 on IN1, 3 on IN2

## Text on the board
Ref Des/Silkscreen Bottom: MODEL:ZRW | DA0ZRWMB6F0 REV:F
Ref Des/Silkscreen Top: DA0ZRWMB6F0 REV:F
User.12: +1.8V_S5 | ADOGND | GND | VIN | +5V | +3V | +1V_S5 | +VCCGT | +VCCCORE | +5V_S5 | +VCCSA | +3V_S5 | +1.05V_GFX | +1.5V_GFX | +VGPU_CORE | EC_GND
User.24: ADOGND | GND
User.45: FIGURE | TYPE | Oblong | Circle | SIZE | 59.0x20.0 | 59.0x28.0 | 71.0x31.0 | 82.0x39.0 | 91.0x28.0 | 94.0x39.0 | 98.0x24.0 | 102.0x31.0 | 120.0x112.0 | 138.0x114.0 | 152.0x93.0 | 10.0 | 12.0 | 14.0 | 22.0 | 24.0 | 28.0 | 31.0 | 32.0 | 35.0 | 118.0 | 134.0 | 140.0 | 142.0 | 161.0 | 217.0 | 252.0 | 37.0 | 39.0 | 43.0 | 47.0 | 55.0 | 63.0 | 67.0 | 197.0 | DRILL CHART: TOP to BOTTOM | ALL UNITS ARE IN MILS | PLATED | NON-PLATED | ROTATION | 0.000 | - | QTY | 7 | 4 | 2 | 1 | 30 | 5087 | 33 | 766 | 19 | 6 | 37 | 18 | 12 | 9 | 3 | 5 | 6019 | TOTAL HOLES:
